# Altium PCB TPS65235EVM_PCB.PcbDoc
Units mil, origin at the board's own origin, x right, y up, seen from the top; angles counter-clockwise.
Board outline 3250 x 2250 mil, 2 copper layers (Top Layer, Bottom Layer), stack 62 mil thick; 65 components, 24 nets, 134 pads, 71 vias.
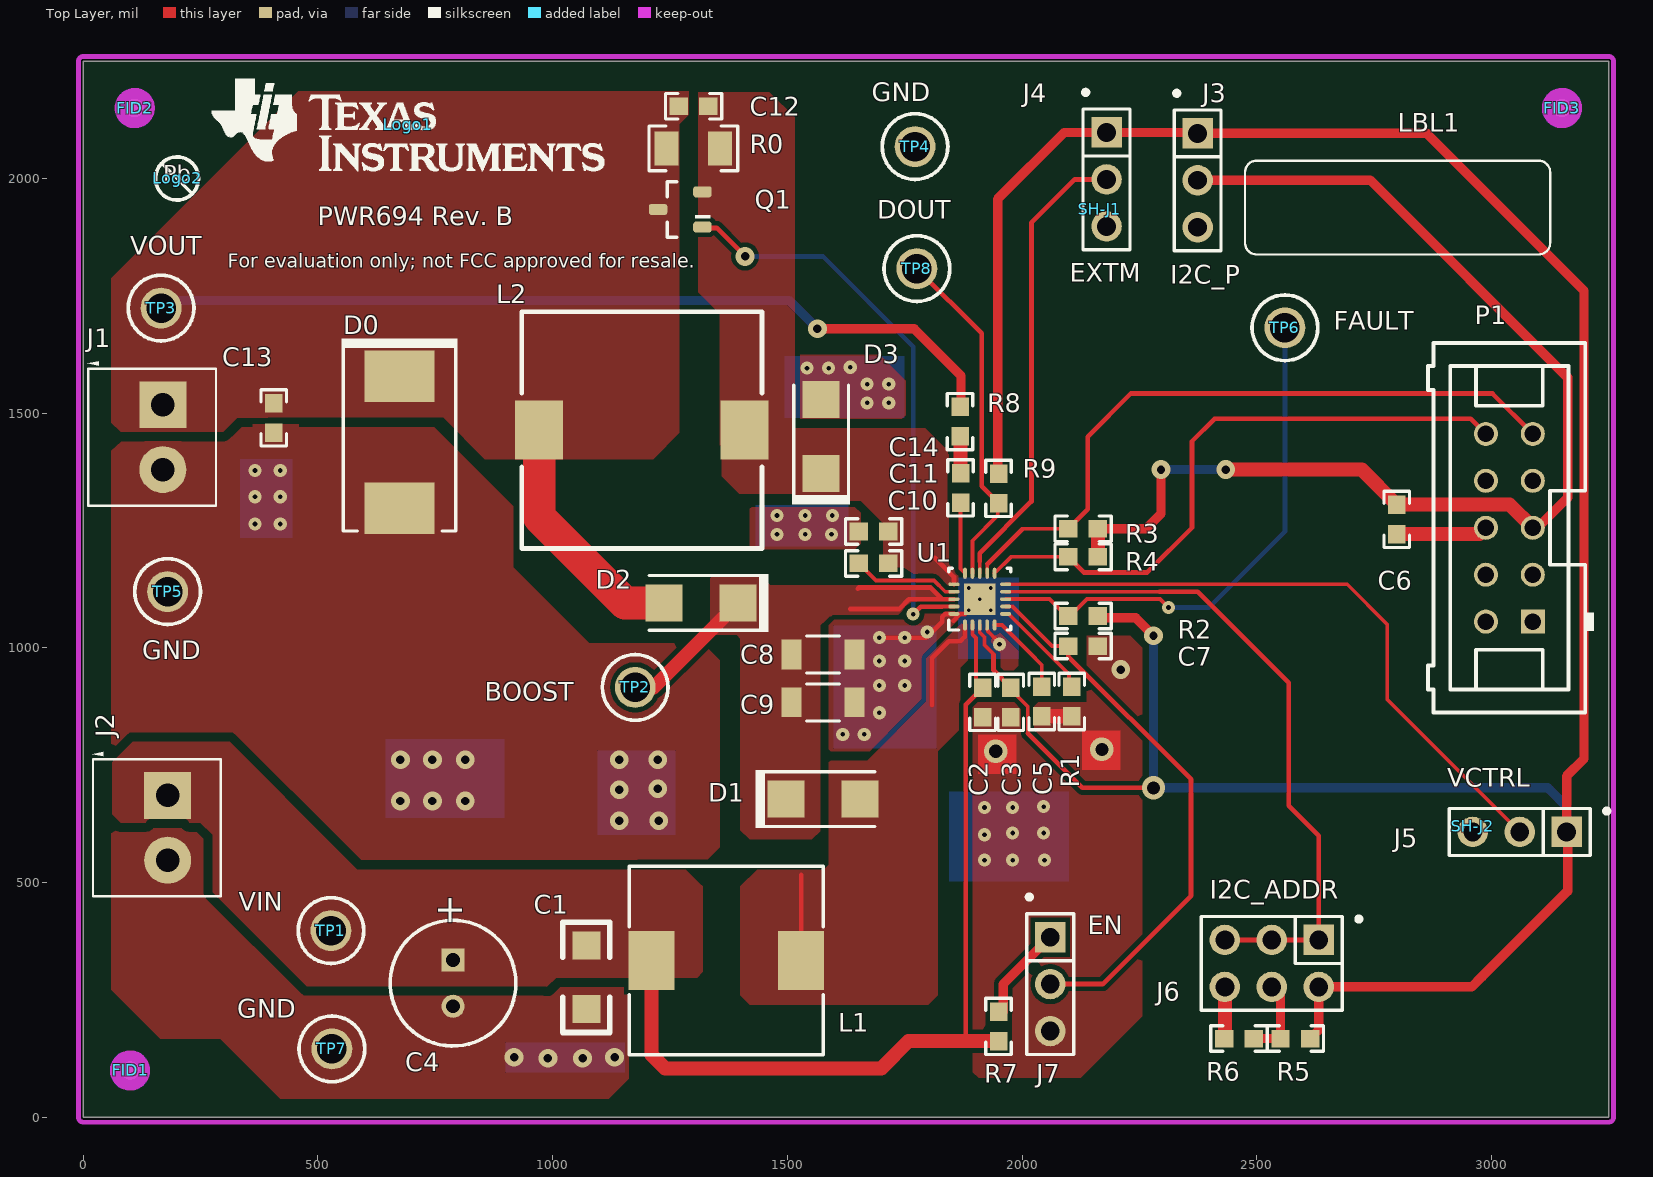
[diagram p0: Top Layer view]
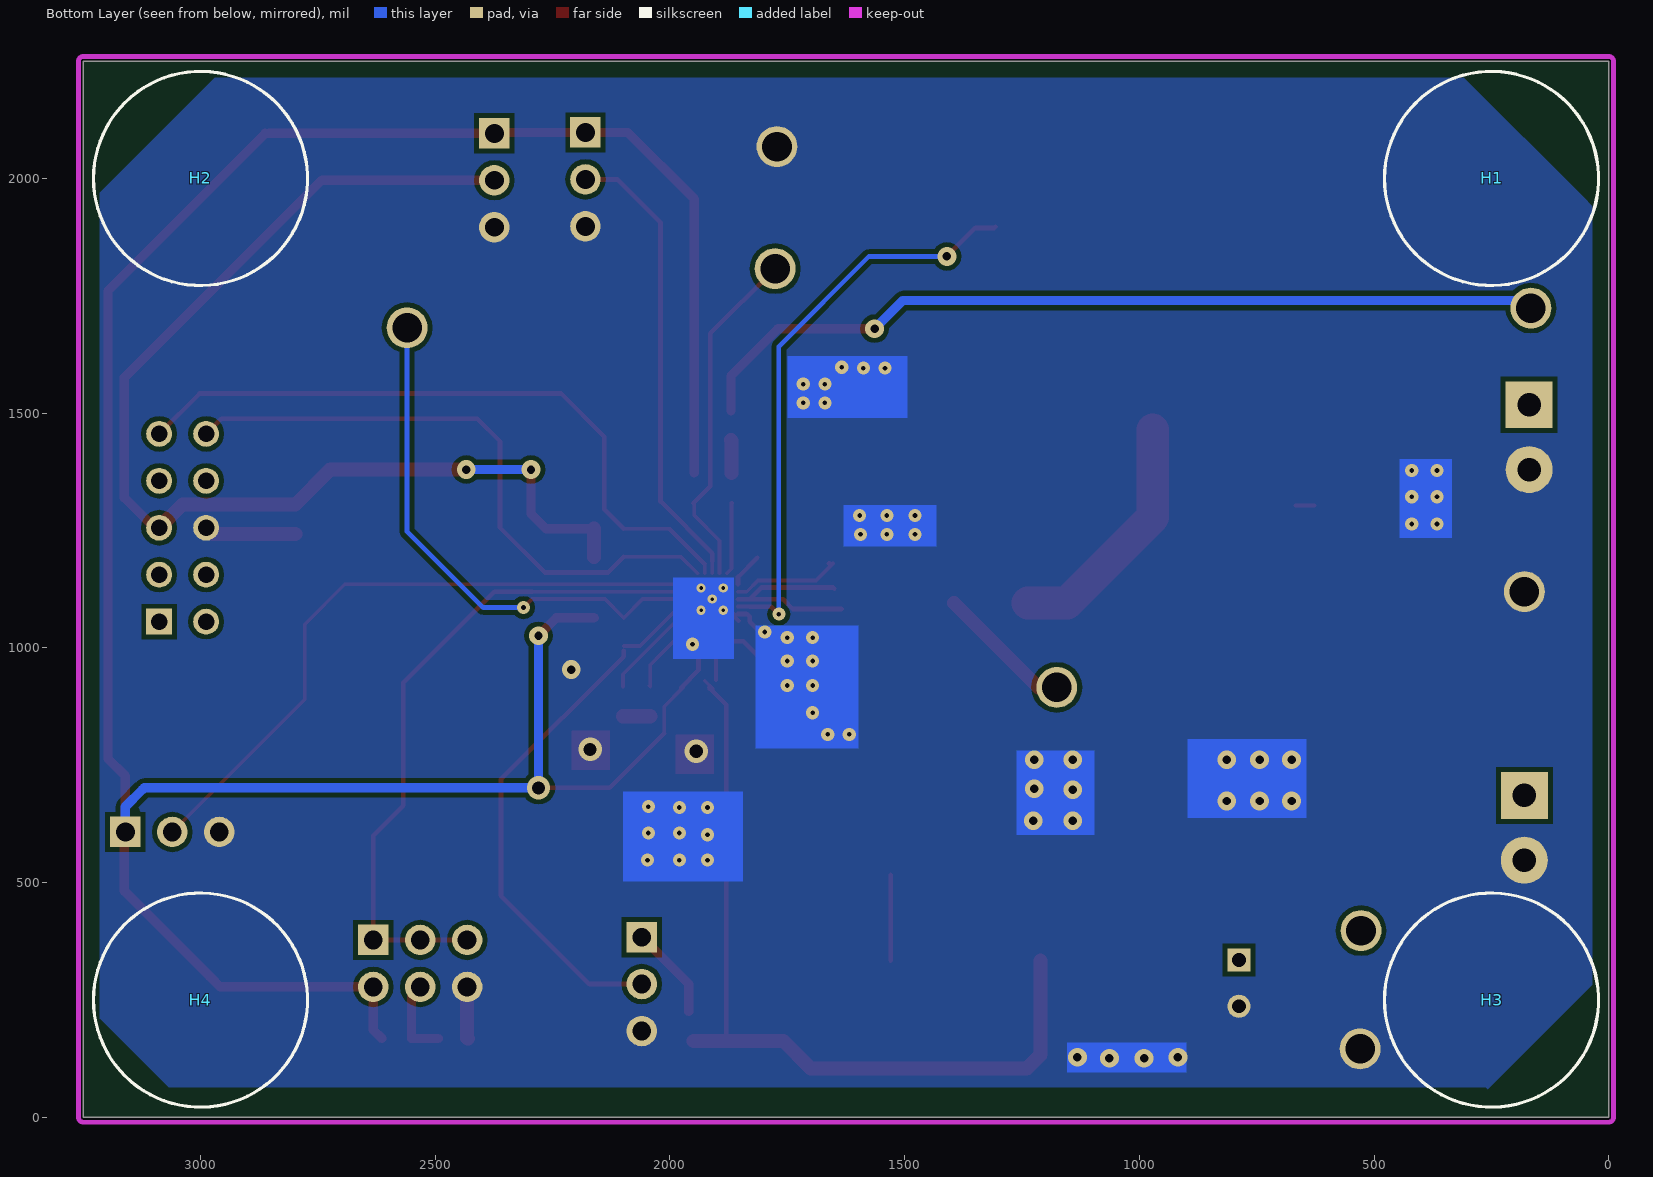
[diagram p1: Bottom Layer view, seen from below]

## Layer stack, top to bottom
Top Solder: solder mask 0.4, Solder Resist, Dk 3.5
Top Layer: signal copper 1.4
Dielectric1: core 59.2, FR-4, Dk 4.8
Bottom Layer: signal copper 1.4
Bottom Solder: solder mask 0.4, Solder Resist, Dk 3.5

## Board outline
0,0 0,2250 3250,2250 3250,0

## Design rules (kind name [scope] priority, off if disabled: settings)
AcuteAngle [All] p1: minimum=4.50000000000000E+0001 checktracksonly=FALSE
AssemblyTestPointUsage [All] p1: valid=2
Clearance Clearance_Keepouts [((IsTrack Or IsArc) And Not InPoly) And IsFree and IsKeepOut vs ((IsTrack Or IsArc) And Not InPoly) And IsFree and IsKeepOut] p1: gap=10
Clearance Clearance_BoardEdge_MountingHoles [OnCopper and InComponentClass('Mounting Holes') vs IsKeepOut] p2: gap=10
Clearance Clearance_BoardEdge_Poly [OnCopper and InPoly vs IsKeepOut] p3: gap=25
Clearance Clearance_BoardEdge [OnCopper and Not InComponentClass('Logo') and not InComponentClass('FiducialMark') and not InRegion(1000,500,4000,800) and Not IsKeepout vs IsKeepOut] p4: gap=30
Clearance Clearance_Poly [InPolygon] p5: gap=10
Clearance [All] p6: gap=6
ComponentClearance ComponentClearance_MountingHoles_FiducialMarks [InComponentClass('Mounting Holes') vs InComponentClass('FiducialMark')] p1: gap=20 collisioncheckmode=3 verticalgap=10 showdistances=FALSE
ComponentClearance ComponentClearance_Shunt [InComponentClass('Header') vs InComponentClass('Shunt')] p2: gap=0 collisioncheckmode=3 verticalgap=0 showdistances=FALSE
ComponentClearance ComponentClearance_Logo [InComponentClass('Logo')] p3: gap=20 collisioncheckmode=3 verticalgap=10 showdistances=FALSE
ComponentClearance ComponentClearance_ScrewToNut [(HasFootprint('NY PMS 440 0025 PH')) vs (HasFootprint('Keystone_1902C'))] p4: gap=5 collisioncheckmode=3 verticalgap=10 showdistances=FALSE
ComponentClearance ComponentClearance_MountingHoles [InComponentClass('Mounting Holes')] p5: gap=20 collisioncheckmode=3 verticalgap=100000 showdistances=FALSE
ComponentClearance ComponentClearance_SmallPassives [HasFootprint('0201*') or HasFootprint('0402*') or HasFootprint('0508') or HasFootprint('0603*') or HasFootprint('0612') or HasFootprint('0805*') or HasFootprint('0815*') or HasFootprint('0830*') or HasFootprint('1206*') or HasFootprint('1210*') or HasFootprint('1808*') or HasFootprint('1812*') or HasFootprint('1825*') or HasFootprint('2010*') or HasFootprint('2220*') or HasFootprint('2225*') or HasFootprint('2512*') or HasFootprint('2728*') or HasFootprint('3518*') vs HasFootprint('0201*') or HasFootprint('0402*') or HasFootprint('0508') or HasFootprint('0603*') or HasFootprint('0612') or HasFootprint('0805*') or HasFootprint('0815*') or HasFootprint('0830*') or HasFootprint('1206*') or HasFootprint('1210*') or HasFootprint('1808*') or HasFootprint('1812*') or HasFootprint('1825*') or HasFootprint('2010*') or HasFootprint('2220*') or HasFootprint('2225*') or HasFootprint('2512*') or HasFootprint('2728*') or HasFootprint('3518*')] p6: gap=20 collisioncheckmode=3 verticalgap=10 showdistances=FALSE
ComponentClearance ComponentClearance_THtoSMT [IsThruComponent vs IsSMTComponent] p7: gap=20 collisioncheckmode=3 verticalgap=30 showdistances=FALSE
ComponentClearance ComponentClearance_THtoTH [IsThruComponent vs IsThruComponent] p8: gap=20 collisioncheckmode=3 verticalgap=30 showdistances=TRUE
ComponentClearance [All] p9: gap=20 collisioncheckmode=3 verticalgap=10 showdistances=FALSE
DiffPairsRouting [All] p1: maxlimit=100 minlimit=10 mostfreqgap=10 toplayer_minwidth=15 toplayer_maxwidth=15 toplayer_prefwidth=15 bottomlayer_minwidth=15 bottomlayer_maxwidth=15 bottomlayer_prefwidth=15 maxuncoupledlength=1000
FabricationTestPointUsage TestPointUsage [All] p1: valid=2 allowmultiple=FALSE
FabricationTestpoint Testpoint [All] p1: side=3 testpointundercomponent=TRUE minsize=40 maxsize=100 preferedsize=60 minholesize=0 maxholesize=40 preferedholesize=32 testpointgrid=1 allowsidetop=TRUE allowsidebottom=TRUE usegrid=TRUE gridtolerance=0.01
FanoutControl Fanout_LCC [IsLCC] p1: bgadir=Out bgaviamode=Centered fanoutstyle=Auto fanoutdirection=Alternating viagrid=1 // Fanout_LCC (Default Rule)
FanoutControl Fanout_BGA [IsBGA] p2: bgadir=Out bgaviamode=Centered fanoutstyle=Auto fanoutdirection=Alternating viagrid=1 // Fanout_BGA (Default Rule)
FanoutControl Fanout_Default [All] p4: bgadir=Out bgaviamode=Centered fanoutstyle=Auto fanoutdirection=Alternating viagrid=1 // Fanout_Default (Default Rule)
FanoutControl Fanout_Small [(CompPinCount < 5)] p5: bgadir=Out bgaviamode=Centered fanoutstyle=Auto fanoutdirection=OutThenIn viagrid=1 // Fanout_Small (Default Rule)
HoleSize [All] p1: absolutevalues=TRUE maxlimit=251 minlimit=6 maxpercent=80.000 minpercent=20.000
HoleToHoleClearance [All] p1: gap=6 allowstackedmicrovias=TRUE
MinimumAnnularRing MinimumAnnularRing_ThermalPadVias [IsVia and InAnyComponent] p1: minimumring=5
MinimumAnnularRing [All] p2: minimumring=5
MinimumSolderMaskSliver MinimumSolderMaskSliver_Logo [InComponentClass('Logo') vs InComponentClass('Logo')] p1: minsoldermaskwidth=0.7
MinimumSolderMaskSliver [All] p2: minsoldermaskwidth=3.94
PlaneClearance [All] p1: clearance=10
PlaneConnect [All] p1: planeconnectstyle=Relief reliefexpansion=10 reliefentries=4 reliefconductorwidth=20 reliefairgap=10
PolygonConnect [All] p1: connectstyle=Direct reliefconductorwidth=20 reliefentries=4 polygonreliefangle="90 Angle" airgapwidth=6
RoutingVias ThermalPadVias [IsVia and InAnyComponent] p1: holewidth=7.87 width=19.68 viastyle="Through Hole" minholewidth=6 minwidth=16 maxholewidth=50 maxwidth=50
RoutingVias [All] p2: holewidth=16 width=34 viastyle="Through Hole" minholewidth=6 minwidth=16 maxholewidth=40 maxwidth=65
SilkToBoardRegionClearance [All] p1 off:
SilkToSilkClearance SilkToSilkClearance_Pb-FreeLogo [(HasFootprint('Pb-Free_Overlay_Medium') OR HasFootprint('Pb-Free_Overlay_Small')) vs (HasFootprint('Pb-Free_Overlay_Medium') OR HasFootprint('Pb-Free_Overlay_Small'))] p1: silktosilkclearance=0
SilkToSilkClearance [All] p2: silktosilkclearance=5
SilkToSolderMaskClearance "Silk to Solder Mask Opening" [IsPad] p1: minsilkscreentomaskgap=1 clearancetoexposedcopper=TRUE
SolderMaskExpansion [All] p1: expansion=1.97
Width [All] p1: maxlimit=100 minlimit=6 preferedwidth=10 checkconnectedcopper=TRUE
13 further rules are at their usual default settings.

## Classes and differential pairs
component class PWR694B_Hardware: !PCB FID1 FID2 FID3 H1 H2 H3 H4 LBL1 Logo1 Logo2 Logo3 SH-J1 SH-J2 ZZ2 ZZ3 ZZ4 ""
component class Header: J3 J4 J5 J6 J7
component class PWR694B: C1 C2 C3 C4 C5 C6 C7 C8 C9 C10 C11 C12 C13 C14 D0 D1 D2 D3 J1 J2 J3 J4 J5 J6 J7 L1 L2 P1 Q1 R0 R1 R2 R3 R4 R5 R6 R7 R8 R9 TP1 TP2 TP3 TP4 TP5 TP6 TP7 TP8 U1
component class FiducialMark: FID1 FID2 FID3
component class AssemblyNote: ZZ2 ZZ3 ZZ4 ""
component class Logo: Logo1
component class Shunt: SH-J1 SH-J2
component class Label: LBL1

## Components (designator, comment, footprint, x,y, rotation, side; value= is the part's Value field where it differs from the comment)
C1 "GRM31CR61E106KA12L" 1206#1 1072,366 r270 top
C2 "GRM188R61E105KA12D" 0603 1916,884 r270 top
C3 "GRM188R61E105KA12D" 0603 1976,884 r270 top
C4 "EEU-EB1E101S" CAPPR250W50D630H1120 788,286 r270 top
C5 "GRM188R71H223KA01D" 0603 2042,886 r90 top
C6 "GRM188R61E105KA12D" 0603 2798,1274 r270 top
C7 "GRM188R71H103KA01D" 0603 2130,1004 r0 top
C8 "C3216X5R1V226M160AC" 1206_180 1576,986 r0 top
C9 "C3216X5R1V226M160AC" 1206_180 1576,884 r0 top
C10 "0603YC104JAT2A" 0603 1684,1180 r0 top
C11 "GRM188R71H104KA93D" 0603 1684,1248 r180 top
C12 "GRM188R71H223KA01D" 0603 1300.31,2154 r180 top
C13 "GRM188R71H104KA93D" 0603 406,1490 r270 top
C14 "GRM188R71H103KA01D" 0603 1869,1341 r90 top
D0 "SMCJ28A" SMC 674,1438 r270 top
D1 "B340A-13-F" SMA 1576,678 r0 top
D2 "B240A-13-F" SMA 1316,1096 r180 top
D3 "B240A-13-F" SMA 1572,1450 r90 top
FID1 "Fiducial" Fiducial10-20 100,100 r0 top
FID2 "Fiducial" Fiducial10-20 110,2150 r0 top
FID3 "Fiducial" Fiducial10-20 3150,2150 r0 top
H1 "SJ-5303 (CLEAR)" Bumpon_SJ5003Transparent 250,2000 r180 bottom
H2 "SJ-5303 (CLEAR)" Bumpon_SJ5003Transparent 3000,2000 r180 bottom
H3 "SJ-5303 (CLEAR)" Bumpon_SJ5003Transparent 250,250 r180 bottom
H4 "SJ-5303 (CLEAR)" Bumpon_SJ5003Transparent 3000,250 r180 bottom
J1 "ED555/2DS" TERM_BLK_ED555-2DS 170,1518 r270 top
J2 "ED555/2DS" TERM_BLK_ED555-2DS 180,686 r270 top
J3 "TSW-103-07-G-S" TSW-103-07-G-S 2374,1996 r270 top
J4 "TSW-103-07-G-S" TSW-103-07-G-S 2180,1998 r270 top
J5 "TSW-103-07-G-S" TSW-103-07-G-S 3060,608 r180 top
J6 "TSW-103-07-G-D" TSW-103-07-G-D 2532,328 r180 top
J7 "TSW-103-07-G-S" TSW-103-07-G-S 2060,284 r270 top
L1 "CLF10040T-100M" CLF10040 1370,334 r0 top
L2 "SLF12565T-221M1R0-PF" SLF12565 1190,1464 r180 top
LBL1 "Size: 0.65\" x 0.20 \"" Label_650x200 2800,1938 r0 top
Logo1 "Texas Instruments" TI_Stacked_Overlay_Small 692,2114 r0 top
Logo2 "Pb-Free Symbol" Pb-Free_Overlay_Small 200,2000 r0 top
Logo3 "FCC disclaimer" FCC_disclaimer 3464,690 r90 top
P1 "XG4C-1031" OMRON_XG4C-1031 3038,1256 r180 top
Q1 "SI2316BDS-T1-E3" SOT-23 1272,1934 r180 top
R0 "CRCW120615R0FKEA" 1206#2 1300,2064 r0 top
R1 "CRCW0603110KFKEA" 0603 2106,886 r90 top
R2 "CRCW0603100KFKEA" 0603 2130,1068 r0 top
R3 "CRCW060310K0JNEA" 0603 2130,1254 r180 top
R4 "CRCW060310K0JNEA" 0603 2130,1194 r180 top
R5 "CRCW060333K0FKEA" 0603 2582,168 r0 top
R6 "CRCW0603100KFKEA" 0603 2462,168 r0 top
R7 "CRCW0603100KFKEA" 0603 1950,194 r270 top
R8 "CRCW060310K0JNEA" 0603 1868,1482 r90 top
R9 "CRCW0603100KFKEA" 0603 1950,1340 r270 top
SH-J1 "969102-0000-DA" SNT-100-BK-G 2166,1934 r90 top
SH-J2 "969102-0000-DA" SNT-100-BK-G 2960,620 r180 top
TP1 "5010" Keystone5010 528,398 r0 top
TP2 "5010" Keystone5010 1176,916 r0 top
TP3 "5010" Keystone5010 166,1724 r90 top
TP4 "5012" Keystone5012 1772,2068 r0 top
TP5 "5012" Keystone5012 180,1120 r90 top
TP6 "5012" Keystone5012 2560,1682 r0 top
TP7 "5012" Keystone5012 530,146 r90 top
TP8 "5012" Keystone5012 1776,1808 r0 top
U1 "TPS65235-1RUKR" RUK0020B 1910,1104 r90 top
ZZ1 "This Assembly Note is for PCB labels only" AssemblyNoteLabel 182.91,3919.84 r0 top
ZZ2 "These assemblies are ESD sensitive, ESD precautions shall be observed." AssemblyNote 185,3829.11 r0 top
ZZ3 "These assemblies must be clean and free from flux and all contaminants. Use of no clean flux is not acceptable." AssemblyNote 185,3740.56 r0 top
ZZ4 "These assemblies must comply with workmanship standards IPC-A-610 Class 2, unless otherwise specified." AssemblyNote 185,3652 r0 top

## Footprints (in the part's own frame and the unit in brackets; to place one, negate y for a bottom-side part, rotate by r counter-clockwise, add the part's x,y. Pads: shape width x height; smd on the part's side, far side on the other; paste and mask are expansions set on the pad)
0603 [mm] "0603 from SM-752 data"
  rect 1x0.95 smd: 1(-0.8,0) 2(0.8,0)
  silkscreen extent -1.52,-0.69 1.52,0.69, body extent -0.87,-0.47 0.87,0.47, height 0.85
1206#1 [mil]
  rect 60x60 smd: 1(0,0) 2(135,0)
  silkscreen extent -50,-50 185,50
1206#2 [mil] "1206 from SM-752 data"
  rect 51.18x72.83 smd: 1(-57.09,0) 2(57.09,0)
  silkscreen extent -94,-48 94,48, body extent -67,-35 67,35, height 53
1206_180 [mm] "1206_180"
  rect 1.1x1.6 smd: 1(-1.7,0) 2(1.7,0)
  silkscreen extent -0.9,-1 0.9,1, body extent -1.75,-0.95 1.75,0.95, height 1.8
AssemblyNote [mil] "Assembly Note"
AssemblyNoteLabel [mil] "Assembly Note for PCB Labels"
Bumpon_SJ5003Transparent [mil] "3M Hemispherical Bumpon transparent"
  round 1 on Mech4: 0(0,0)
  silkscreen extent -228,-228 228,228, body extent -217,-218 219,218, height 197
CAPPR250W50D630H1120 [mm] "PANASONIC"
  rect 1.25x1.25 hole 0.75: 1(-1.25,0)
  round 1.25 hole 0.75: 2(1.25,0)
  silkscreen extent -3.4,-3.4 3.4,3.4, body extent -3.37,-3.39 3.4,3.39, height 12.21
CLF10040 [mm] "TDK"
  rect 2.5x3.2 smd: 1(-4.05,0) 2(4.05,0)
  silkscreen extent -5.25,-5.1 5.25,5.1, body extent -5.15,-5 5.15,5, height 4.1
FCC_disclaimer [mil]
Fiducial10-20 [mm]
  round 1 smd mask+0.5: 1(0,0)
  Top Layer keep-out circle w1.178: c0,0 r0.5
Keystone5010 [mil] "Keystone Multipurpose loops"
  round 87 hole 63: 1(0,0)
  silkscreen extent -70,-70 70,70, body extent -63,-63 63,62, height 319
Keystone5012 [mil] "Keystone Multipurpose loops"
  round 87 hole 63: 1(0,0)
  silkscreen extent -70,-70 70,70, body extent -63,-63 63,62, height 319
Label_650x200 [mil] "Thermal Transfer Label"
  round 1 on Mech13: 0(0,0)
  silkscreen extent -325,-100 325,100, body extent -325,-100 325,100, height 1
OMRON_XG4C-1031 [mm] "TH, 10-Leads, Body 8.5x20mm, Pitch 2.54mm"
  rect 1.3x1.3 / inner round 1.4 / far side rect 1.4x1.4 hole 0.9: 1(-1.27,5.08)
  round 1.3 / inner round 1.4 / far side round 1.4 hole 0.9: 2(1.27,5.08) 3(-1.27,2.54) 4(1.27,2.54) 5(-1.27,0) 6(1.27,0) 7(-1.27,-2.54) 8(1.27,-2.54) 9(-1.27,-5.08) 10(1.27,-5.08)
  silkscreen extent -4.57,-10 4.4,10, body extent -4.1,-10 4.4,10, height 9.02
Pb-Free_Overlay_Small [mil]
  silkscreen extent -46,-46 46,46
RUK0020B [mm]
  oval 0.6x0.2 smd: 1(-1.4,0.8) 2(-1.4,0.4) 3(-1.4,0) 4(-1.4,-0.4) 5(-1.4,-0.8) 11(1.4,-0.8) 12(1.4,-0.4) 13(1.4,0) 14(1.4,0.4) 15(1.4,0.8)
  oval 0.2x0.6 smd: 6(-0.8,-1.4) 7(-0.4,-1.4) 8(0,-1.4) 9(0.4,-1.4) 10(0.8,-1.4) 16(0.8,1.4) 17(0.4,1.4) 18(0,1.4) 19(-0.4,1.4) 20(-0.8,1.4)
  rect 1.7x1.7 smd paste-0.85: 21(0,0)
  silkscreen extent -1.68,-1.68 1.68,1.68, body extent -1.55,-1.55 1.55,1.55, height 0.81
SLF12565 [mm] "TDK recommended land pattern"
  rect 2.6x3.2 smd: 1(-5.55,0) 2(5.55,0)
  silkscreen extent -6.5,-6.4 6.5,6.4, body extent -6.4,-6.4 6.4,6.4, height 6.85
SMA [mm] "Molded Diode, 2-Leads, Body 4.3x2.6mm, IPC Medium Density, based on OnSemi component dimensions and land pattern"
  rect 2x2 smd: 1(-2,0) 2(2,0)
  silkscreen extent -3.66,-1.57 2.79,1.57, body extent -2.6,-1.3 2.6,1.3, height 2.42
SMC [mil] "Molded Diode, 2-Leads, Body 6.9x5.8mm, IPC Medium Density, based on OnSemi component dimensions and land patterns"
  rect 110x150 smd: 1(-140.49,0) 2(140.49,0)
  silkscreen extent -221,-124 189,123, body extent -156,-116 156,116, height 91
SNT-100-BK-G [mil] "Samtec STEP model"
  round 1 on Mech3: 0(0,0)
  body extent -100,-50 100,50, height 344
SOT-23 [mm] "SOT23, 3-Leads, Body 2.9x1.3mm, Pitch 0.95mm, Lead Span 2.5mm, IPC Medium Density"
  rrect50% 1x0.6 smd: 1(-1.2,0.95) 2(-1.2,-0.95) 3(1.2,0)
  silkscreen extent -1.63,-1.5 0.7,1.5, body extent -1.16,-1.45 1.21,1.45, height 1
TERM_BLK_ED555-2DS [mil]
  rect 100x100 hole 50: 1(0,0)
  round 100 hole 50: 2(138,0)
  silkscreen extent -93,-161 215,113, body extent -69,-150 207,106, height 323
TI_Stacked_Overlay_Small [mil]
  silkscreen extent -418,-98 418,98
TSW-103-07-G-D [mm] "Samtec 100mil, 2x3, 230 mil above insulator"
  rect 1.65x1.65 hole 1.016: 1(-2.54,-1.27)
  round 1.65 hole 1.016: 2(-2.54,1.27) 3(0,-1.27) 4(0,1.27) 5(2.54,-1.27) 6(2.54,1.27)
  silkscreen extent -4.84,-2.54 3.81,2.54, body extent -3.81,-2.54 3.81,2.54, height 8.38
TSW-103-07-G-S [mm] "Samtec 100mil, 1x3, 230 mil above insulator"
  rect 1.65x1.65 hole 1.016: 1(-2.54,0)
  round 1.65 hole 1.016: 2(0,0) 3(2.54,0)
  silkscreen extent -4.83,-1.27 3.81,1.27, body extent -3.81,-1.27 3.81,1.27, height 8.38

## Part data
C1: "CAP, CERM, 10 μF, 25 V, +/- 10%, X5R, 1206"
C2 C3 C6: "CAP, CERM, 1 μF, 25 V, +/- 10%, X5R, 0603"
C4: "CAP, AL, 100 μF, 25 V, +/- 20%, TH"
C5 C12: "CAP, CERM, 0.022 μF, 50 V, +/- 10%, X7R, 0603"
C7 C14: "CAP, CERM, 0.01 μF, 50 V, +/- 10%, X7R, 0603"
C8 C9: "CAP, CERM, 22 μF, 35 V, +/- 20%, X5R, 1206"
C10: "CAP, CERM, 0.1 μF, 16 V, +/- 5%, X7R, 0603"
C11 C13: "CAP, CERM, 0.1 μF, 50 V, +/- 10%, X7R, 0603"
D0: "Diode, TVS, Uni, 28 V, 1500 W, SMC"
D1: "Diode, Schottky, 40 V, 3 A, SMA"
D2 D3: "Diode, Schottky, 40 V, 2 A, SMA"
FID1 FID2 FID3: "Fiducial mark.  There is nothing to buy or mount."
H1 H2 H3 H4: "Bumpon, Hemisphere, 0.44 X 0.20, Clear"
J1 J2: "Terminal Block, 6A, 3.5mm Pitch, 2-Pos, TH"
J3 J4 J5 J7: "Header, 100mil, 3x1, Gold, TH"
J6: "Header, 100mil, 3x2, Gold, TH"
L1: "Inductor, Shielded, Ferrite, 10 μH, 4 A, 0.0312 ohm, SMD"
L2: "Inductor, Shielded, Ferrite, 220 μH, 1.2 A, 0.273 ohm, SMD"
LBL1: library part THT-14-423-10, "Thermal Transfer Printable Labels, 0.650\" W x 0.200\" H - 10,000 per roll"
Logo1: library part TI_Logo, "Texas Instrument Corporate Signature"
Logo2: library part Pb-Free
Logo3: library part FCC_disclaimer, "FCC_disclaimer"
P1: "Header (shrouded), 100mil, 5x2, Gold, TH"
Q1: "MOSFET, N-CH, 30 V, 4.5 A, SOT-23"
R0: "RES, 15.0, 1%, 0.25 W, 1206"
R1: "RES, 110 k, 1%, 0.1 W, 0603"
R2 R6 R7 R9: "RES, 100 k, 1%, 0.1 W, 0603"
R3 R4 R8: "RES, 10 k, 5%, 0.1 W, 0603"
R5: "RES, 33.0 k, 1%, 0.1 W, 0603"
SH-J1 SH-J2: "Shunt, 100mil, Gold plated, Black"
TP1 TP2 TP3: "Test Point, Multipurpose, Red, TH"
TP4 TP5 TP6 TP7 TP8: "Test Point, Multipurpose, White, TH"
U1: "LNB VOLTAGE REGULATOR WITH I2C INTERFACE, RUK0020B"
ZZ1: library part AssemblyNoteLabel
ZZ2 ZZ3 ZZ4: library part AssemblyNote

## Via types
v1: diameter 28, hole 10, Top Layer to Bottom Layer, 41 vias
v2: diameter 40, hole 18, Top Layer to Bottom Layer, 22 vias
v3: diameter 19.68, hole 7.87, Top Layer to Bottom Layer, 5 vias
v4: diameter 50, hole 28, Top Layer to Bottom Layer, 3 vias

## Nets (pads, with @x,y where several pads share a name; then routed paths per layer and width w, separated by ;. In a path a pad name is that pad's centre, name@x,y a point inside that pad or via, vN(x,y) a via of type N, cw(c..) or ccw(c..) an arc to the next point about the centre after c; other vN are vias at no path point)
ADDR: J6.1 J6.3 J6.5 U1.9 | length 1457.6
  Top Layer w8: U1.9 2292,1119.75
  Top Layer w10: 2292,1119.75 2374.25,1119.75 2568,926 2568,664 2632,600 J6.1 J6.3 J6.5
BOOST: C8.1 C9.1 D1.1 D2.1 TP2.1 U1.18 | length 714.1
  Top Layer w10: 1634,1082.93 1738,1082.93 1759.07,1104 1829.81,1104 ; 1650,1126 1652.71,1128.71 1805.11,1128.71 1829.81,1104 ; U1.18 1829.81,1104
  Top Layer w30: TP2.1 1214.74,916 D2.1
DIN: C14.1 U1.15 | length 155.7
  Top Layer w8: C14.1@1868,1308.5 C14.1 1869,1168.62 U1.15
DOUT: R9.2 TP8.1 U1.14 | length 744.2
  Top Layer w8: U1.14 1894.25,1228.25 1948,1282 R9.2@1948,1309.5
  Top Layer w10: TP8.1 1914,1670 1914,1344.5 R9.2
EN: C7.1 J7.2 U1.7 | length 1176.5
  Top Layer w8: U1.7 1979.75,1088.25 2064,1004 C7.1
  Top Layer w10: J7.2 2172,284 2360,472 2360,720 2098.5,981.5 C7.1@2098.5,994
EXTM: J4.2 U1.13 | length 990.6
  Top Layer w8: U1.13 1910,1184
  Top Layer w10: 1910,1184 1910,1202 2020,1312 2020,1906 2112,1998 J4.2
FAULT: R2.1 TP6.1 U1.8 | length 1136.6
  Top Layer w8: U1.8 2058.5,1104 2098.5,1064 2138.5,1104 2294,1104 v1(2312,1086)
  Bottom Layer w10: v1(2312,1086) 2398,1086 2560,1248 TP6.1
GDR: Q1.1 U1.19 | length 1231
  Top Layer w8: 1829.37,1088.25 U1.19
  Top Layer w10: Q1.1@1306.35,1897.5 1309.26,1894.6 1349.4,1894.6 v2(1410,1834) ; v1(1768,1072) 1784,1088 1829.37,1088
  Bottom Layer w10: v2(1410,1834) 1576,1834 1768,1642 v1(1768,1072)
GND: C1.2 C2.2 C3.2 C4.2 C5.1 C6.2 C7.2 C8.2 C9.2 C11.2 C13.2 D0.2 D3.2 J1.2 J2.2 J3.3 J4.3 J5.3 J6.6 J7.3 P1.6 R1.1 R6.1 TP4.1 TP5.1 TP7.1 U1.4 U1.20 U1.21 | length 732
  Top Layer w8: D0.2@627,1303.51 D0.2@668,1303.51 ; U1.21@1878.5,1072.5 v3(1886.38,1080.38) v3(1910,1104) ; U1.4@1926,1041.59 1926,1037.6 1927.56,1036.04 1927.56,1035.24 1935.72,1027.07 ; 1936,1026.79 1952,1010.79 1952,996 1946,1002 v1(1952,1008)
  Top Layer w10: v1@1706.93,1022 1796,1022 1830,1056 1830,1066 1836.5,1072.5 U1.20 ; 1854,1058 1864.5,1068.5 1864.5,1072.5 U1.21@1878.5,1072.5 ; v4(2170,784) v4@2170,784.5
  Top Layer w30: D3.2 D3.2@1572,1530 ; C5.1 R1.1@2100,854.5 ; R6.1 2432,169.5 J6.6 ; C6.2 2974.5,1242.5 P1.6
  other v1: 1920,548 1980,548 2048,548 1920,602 1980,606 2046,606 1920,660 1980,660 2046,662 1618,816 1664,816 1696,862 1696,920 1750,920 1696,972 1750,972 1696,1022 1750,1022 1798,1034 1478,1242 1538,1242 1594,1242 366,1264 420,1264 1478,1282 1538,1282 1596,1282 366,1322 420,1322 366,1378 420,1378 1670,1522 1716,1522 1670,1562 1716,1562 1542,1596 1588,1596 1634,1598
  other v2: 990,126 1064,126 918,128 1132,128 1142,632 1226,632 676,674 744,674 814,674 1142,698 1224,700 676,762 744,762 814,762 1142,762 1224,762 2210,954
  other v3: 1933.62,1080.38 1886.38,1127.62 1933.62,1127.62
  other v4: 1944,780
ISET: R1.2 U1.6 | length 214.6
  Top Layer w8: U1.6 1971.5,1072.5 2070,974 2100,944 R1.2@2100,917.5
LX: D1.2 L1.2 U1.1 | length 396.7
  Top Layer w10: L1.2 1529.45,516.55 ; 1808,878 1808,978 1844,1014 1868,1014 1878.5,1024.5 U1.1
NetC14_2: C14.2 R8.1 | length 70.4
  Top Layer w30: C14.2 1869,1441.5 R8.1@1870,1442.5
NetJ6_4: J6.4 R5.1 R6.2 | length 174.7
  Top Layer w20: R6.2 R5.1 2550.5,259.5 J6.4
NetJ7_1: J7.1 R7.1 | length 199.9
  Top Layer w20: R7.1@1960,225.5 1960,284 J7.1
SCL: P1.9 R3.2 U1.12 | length 1457.8
  Top Layer w8: U1.12 1925.75,1178.53 1926.56,1179.35 ; 2000,1254 R3.2
  Top Layer w10: 1926.56,1179.35 2000,1252.79 ; R3.2 2140,1295.5 2140,1449.99 2232.01,1541.99 3002.01,1541.99 P1.9
SDA: P1.10 R4.2 U1.11 | length 1331.2
  Top Layer w8: U1.11 1976.38,1194 R4.2
  Top Layer w10: R4.2 2131.63,1160.87 2266.87,1160.87 2362,1256 2362,1440 2410,1488 2956,1488 P1.10
TCAP: C5.2 U1.5 | length 185
  Top Layer w8: U1.5 1957.12,1048.88 2016,990 2042,964 C5.2 C5.2@2044,919.5
V3V: C6.1 J3.2 P1.5 R3.1 R4.1 | length 2471.6
  Top Layer w10: P1.5 P1.5@3098,1256
  Top Layer w20: R3.1 2264,1254 2296,1286 v2(2296,1380) ; J3.2@2364,2002 J3.2@2372,2002 ; J3.2 2742,1996 3162,1576 3162,1320 P1.5@3098,1256
  Top Layer w30: R4.1 R3.1 ; v2(2434,1380) 2723.5,1380 C6.1 3038.5,1305.5 P1.5
  Bottom Layer w20: v2(2296,1380) v2(2434,1380)
VCC: C3.1 J3.1 J4.1 J5.1 J6.2 R2.2 R5.2 R9.1 U1.3 | length 6026.9
  Top Layer w8: U1.3 1910,1033 1920,1023 1920,1006.06 1940,986.06 ; C3.1@1972,915.5 2012,875.5 2012,818
  Top Layer w10: 1939.29,985.35 1939.29,952.2 C3.1 ; R9.1@1948,1373.5 R9.1 ; 2012,818 2128,702 v4(2280,702) ; J3.1@2360,2098 J3.1@2364,2102 ; 2854,2096 2862,2096 ; J5.1@3162,606 J5.1@3162.29,607.58
  Top Layer w20: R9.1@1948,1373.5 1948,1956 2090,2098 J4.1 J3.1@2360,2098 ; R2.2@2161.5,1064 2242,1064 v2(2280,1026) ; J3.1 2854,2096 ; R5.2 2632,186.5 J6.2 2958,278 2980,300 3162,482 J5.1@3162,606 ; 2862,2096 3197,1761 3197,764 3160,727 J5.1
  Bottom Layer w10: 3120,702 3124,698
  Bottom Layer w20: v4(2280,702) 3120,702 ; v4@2280,724 v2(2280,1026) ; 3124,698 3160,662 J5.1
VCP: C10.1 U1.17 | length 228
  Top Layer w8: C10.1 1688.8,1143.71 1696.64,1143.71 1812.29,1143.71 1836.25,1119.75 U1.17
  Top Layer w10: C10.1@1660.35,1180 C10.1@1661.05,1180
VCTRL: J5.2 U1.10 | length 1407.1
  Top Layer w8: U1.10 2540.5,1135.5 2692.5,1135.5 2778,1050 2778,890 J5.2
VIN: C1.1 C2.1 C4.1 J2.1 L1.1 R7.2 TP1.1 U1.2 | length 1892.1
  Top Layer w8: U1.2 1894.25,1028.94 1902,1021.2 C2.1@1902,932 ; C2.1@1909.5,913.5 C2.1@1926,930 ; C2.1@1916,912 C2.1
  Top Layer w10: 1878,162.5 1880,164.5 1880,879.5 C2.1
  Top Layer w30: L1.1 1210.55,133.45 1240,104 1700,104 1758.5,162.5 1878,162.5 R7.2
VLNB: C10.2 C11.1 C12.1 D3.1 L2.1 Q1.2 R0.2 U1.16 | length 73.4
  Top Layer w10: 1814,1192 1854.88,1151.12 U1.16
VOUT: C12.2 C13.1 D0.1 D2.2 J1.1 L2.2 Q1.3 R0.1 R8.2 TP3.1 | length 2360
  Top Layer w10: L2.2@971.26,1463.76 L2.2
  Top Layer w20: v2@1572,1680 1770,1680 1870,1580 R8.2@1870,1505.5
  Top Layer w70: L2.2 971.5,1278.5 1154,1096 D2.2
  Bottom Layer w20: TP3.1@170,1740 1504,1740 v2(1564,1680)
pads on no net: FID1.1 FID2.1 FID3.1 H1.0 H2.0 H3.0 H4.0 LBL1.0 P1.1 P1.2 P1.3 P1.4 P1.7 P1.8 SH-J1.0 SH-J2.0

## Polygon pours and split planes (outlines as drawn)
GND on Top Layer "Top Layer-No Net 10" (solid, remove dead copper, pour order 40): 60,1420 90,1450 318,1450 348,1480 738,1480 748.39,1469.61 916,1302 916,1172 1078,1010 1320,1010 1356,974 1356,576 1330,550 1180,550 1180,546 1162,528 1162,534 1162,82 1160,80 1120,40 420,40 292,168 164,168 162,170 60,272 60,1420 90,1450 92,1450
BOOST on Top Layer "Top Layer-No Net 8" (solid, remove dead copper, pour order 35): 1850,1110 1832,1110 1808,1134 1474,1134 1464,1134 1444,1154 1342,1154 1336,1148 1336,1048 1336,1040 1348,1028 1392,1028 1400,1020 1560,1020 1560,1038 1590,1068 1732,1068 1734,1068 1762,1096 1764,1098 1850,1098 1850,1110
GND on Top Layer "Top Layer-No Net 5" (solid, remove dead copper, pour order 32): 1530,1300 1424,1300 1420,1296 1420,1216 1420,1214 1424,1210 1534,1210 1534,1296 1530,1300
BOOST on Top Layer "Top Layer-No Net 3" (solid, remove dead copper, pour order 27): 1848,1108 1832,1108 1456,1108 1444,1108 1436,1100 1400,1064 1400,612 1420,592 1546,592 1552,592 1570,610 1570,1048 1594,1072 1598,1076 1736,1076 1738,1076 1762,1100 1848,1100 1848,1108
GND on Top Layer "Top Layer-No Net" (solid, remove dead copper, pour order 24): 1874,1080 1790,1080 1770,1060 1696,1060 1600,1060 1588,1048 1588,1046 1588,784 1592,780 1680,780 1770,870 1786,886 1786,980 1874,1068 1874,1080
GND on Top Layer "Top Layer-No Net 12" (solid, remove dead copper, pour order 34): 1528,1618 1528,1488 1744,1488 1750,1494 1752,1496 1752,1578 1752,1584 1714,1622 1712,1624 1528,1624 1528,1618
GND on Top Layer "Top Layer-No Net 21" (solid, remove dead copper, pour order 31): 952,198 1154,198 1162,190 1162,94 956,94 952,98 868,198
GND on Top Layer "Top Layer-No Net 9" (solid, remove dead copper, pour order 30): 361,1476 361,1470.93 333,1435.45 329,1430.38 329,1222.53 455,1222.53 457,1220 459,1222.53 459,1476 361,1476
VLNB on Top Layer "Top Layer-No Net 19" (solid, remove dead copper, pour order 29): 1596,1468 1768,1468 1794,1468 1828,1434 1844,1418 1844,1190 1844,1172 1842,1174 1704,1174 1704,1266 1656,1314 1514,1314 1514,1468 1598,1468
VLNB on Top Layer "Top Layer-No Net 18" (solid, remove dead copper, pour order 28): 1360,1468 1360,1366 1398,1328 1624,1328 1634,1328 1634,1430 1634,1432 1614,1452 1598,1468 1360,1468
GND on Top Layer "Top Layer-No Net 4" (solid, remove dead copper, pour order 25): 1924,1034 1924,976 1924,974 1944,954 1946,952 1970.69,952 1982,952 1990,960 1992,962 1992,1012 1964,1040 1962,1042 1924,1042 1924,1028
GND on Top Layer "Top Layer-No Net 13" (solid, remove dead copper, pour order 37): 1546,1300 1528,1282 1528,1274 1528,1234 1528,1230 1540,1218 1566,1218 1652,1218 1654,1220 1656,1222 1656,1274 1656,1288 1644,1300 1548,1300
GND on Top Layer "Top Layer-No Net 16" (solid, remove dead copper, pour order 39): 1878,686 1878,432 1886,424 1904,406 2126,406 2128,406 2154,432 2252,530 2252,696 2252,698 2194,756 2182,744 1878,744 1878,680
VOUT on Top Layer "Top Layer-No Net 11" (solid, remove dead copper, pour order 33): 60,1480 80,1460 298,1460 302,1464 328,1490 342,1490 768,1490 856,1402 1178,1402 1214,1402 1270,1458 1270,2116 1290,2136 1290,2186 458,2186 60,1788
VIN on Top Layer "Top Layer-No Net 14" (solid, remove dead copper, pour order 36): 62,756 104,798 106,800 308,800 312,800 548,564 584,528 1282,528 1284,528 1314,498 1320,492 1320,312 1320,310 1308,298 1032,298 1008,298 988,278 986.53,279.47 476.53,279.47 276,480 276,602 250,628 80,628 62,646 62,756
VLNB on Top Layer "Top Layer-No Net 20" (solid, remove dead copper, pour order 41): 1864,1134 1801.86,1134 1778,1158 1768,1158 1754.63,1167.66 1746.72,1171.63 1704,1171.63 1714.66,1165.9 1704,1174.83 1704,1208 1752,1208 1766,1222 1768,1224 1844,1224 1844,1178 1864,1158
GND on Top Layer "Top Layer-No Net 22" (solid, remove dead copper, pour order 43): 1514,1280 1514,1284 1530,1300 1644,1300 1656,1288 1656,1222 1648,1214 1644,1210 1528,1210 1524,1210 1514,1220 1514,1286
GND on Top Layer "Top Layer-No Net 25" (solid, remove dead copper, pour order 44): 2138,1026 2230,1026 2242,1014 2256,1000 2256,820 2138,820 2138,1026
GND on Top Layer "Top Layer-No Net 26" (solid, remove dead copper, pour order 45): 1906.13,884 1895.29,873.16 1895.29,96.71 1908,84 1908.81,84.81 2121.19,84.81 2124.81,84.81 2230,190 2256,216 2256,858.69 2256,864 2236,884 1906.13,884
VLNB on Top Layer "Top Layer-No Net 2" (solid, remove dead copper, pour order 42): 1312,2184 1420,2184 1462,2184 1516,2130 1516,1432 1356,1432 1356,1710 1356,1712 1312,1756 1310,1758 1310,2184
LX on Top Layer "Top Layer-No Net 6" (solid, remove dead copper, pour order 53): 1872,1056 1884,1056 1884,974 1868,958 1868,828 1864.71,824.71 1820,780 1820,260 1800,240 1420,240 1400,260 1400,492 1436,528 1572,528 1578,528 1588,538 1588,756 1592,760 1670,760 1796,886 1796,977.65 1796,980 1872,1056
GND on Bottom Layer "Bottom Layer-No Net 1" (solid, remove dead copper, pour order 38): 1634,912 1750,912 1750,806 1746,810 1634,810 1634,912
GND on Bottom Layer "Bottom Layer-No Net" (solid, remove dead copper, pour order 51): 556.28,2214.7 308.7,2214.7 54,1960 34,1940 34,310 34,284 258,60 262,64 3066,64 3068,64 3214,210 3214.7,210.7 3214.7,1970.09 2970.09,2214.7 2964.79,2220 556,2220

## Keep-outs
Keep-Out Layer:
  lines w10: -2,2260 3248,2260 ; 0,2260 ccw(c0,2250) -10,2250 -10,0 ; 3250,2260 cw(c3250,2250) 3260,2250 3260,0 ; -10,0 ccw(c0,0) 0,-10 ; -10,0 ccw(c0,0) 0,-10 ; 0,-10 3250,-10 ; 3250,-10 ccw(c3250,0) 3260,0 ; 3250,-10 ccw(c3250,0) 3260,0
  text ".Layer_Name" at 577,-858.49 h60

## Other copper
Top Layer:
  rectangle net BOOST: 1830,1100 1850,1108
  rectangle net GND: 1906,732 1988,816
  rectangle net GND: 2128,740 2210,824
  text ".Layer_Name" at 577,-858.49 h60
Bottom Layer:
  rectangle net GND: 1096,602 1262,782
  rectangle net GND: 1864,976 1994,1150
  rectangle net GND: 1432,1216 1630,1304
  rectangle net GND: 900,96 1154,160
  rectangle net GND: 1844,502 2100,694
  rectangle net GND: 1598,786 1818,1048
  rectangle net GND: 334,1234 446,1402
  rectangle net GND: 1494,1490 1750,1622
  rectangle net GND: 644,638 898,806
  text "SVN:" at 4400,288 h60
  text ".VersionControl_RevNumber" at 4498,100 h60
  text ".Layer_Name" at 577,-858.49 h60

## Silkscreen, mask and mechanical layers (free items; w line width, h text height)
Top Overlay:
  text "GND" at 1680,2164 h40
  text "DOUT" at 1692,1914 h40
  text "PWR694 Rev. B" at 500,1900 h40
  text "VOUT" at 100,1838 h40
  text "EXTM" at 2102,1780 h40
  text "I2C_P" at 2316,1776 h40
  text "FAULT" at 2664,1678 h40
  text "GND" at 126,976 h40
  text "BOOST" at 856,888 h40
  text "VCTRL" at 2906,704 h40
  text "I2C_ADDR" at 2400,466 h40
  text "VIN" at 332,440 h40
  text "EN" at 2140,390 h40
  text "GND" at 328,212 h40
  text ".Layer_Name" at 577,-858.49 h60
Bottom Overlay:
  text ".Layer_Name" at 577,-858.49 h60
Top Paste:
  text ".Layer_Name" at 577,-858.49 h60
Bottom Paste:
  text ".Layer_Name" at 577,-858.49 h60
Top Solder:
  text ".Layer_Name" at 577,-858.49 h60
  text ".Layer_Name" at 577,-858.49 h60
Bottom Solder:
  text ".Layer_Name" at 577,-858.49 h60
Drill Guide:
  text ".Layer_Name" at 577,-858.49 h60
M1 Board Outline:
  lines w10: 0,0 3250,0 3250,2250 0,2250 0,0 ; 2500,-5 ccw(c2500,0) 2505,0 cw(c2500,0) 2500,-5
  text ".Layer_Name" at 577,-858.49 h60
M2 Board Dimensions:
  rectangle: 0,-275 125,-150
  rectangle: 125,-400 500,-275
  lines w7: 0,-275 1000,-275 ; 125,-400 125,-150 ; 250,-400 250,-150 ; 500,-400 500,-150 ; 750,-400 750,-150 ; 0,-400 1000,-400 1000,-150 0,-150 0,-400
  text ".Layer_Name" at 577,-858.49 h60
M3 3D STEP Top:
  text ".Layer_Name" at 577,-858.49 h60
M4 3D STEP Bottom:
  text ".Layer_Name" at 577,-858.49 h60
M5 Assembly Top:
  lines w10: -292,-930.17 6308,-930.17 ; -292,-726.83 6310,-726.83 ; -292,-523.5 -292,-1133.5 3713,-1133.5 6310,-1133.5 6310,-523.5 -291.5,-523.5 -291.5,-1133.5 1284,-1133.5 ; 2173,-1133.5 2173,-523.5 ; 3440,-726.83 3440,-523.5 ; 4280,-726.83 4280,-523.5 ; 4902,-1140 4902,-937.17
  text "COMPONENTS MARKED 'DNP' SHOULD NOT BE POPULATED." at 1153.5,-318.5 h60
  text "ASSEMBLY VARIANT:" at 1153,-434 h60
  text ".VariantName" at 2189,-434 h60
  text "PCB VIEWED FROM TOP SIDE" at -228.5,-655.67 h60
  text "BOARD #:" at 2248,-655.67 h60
  text ".PRJ_Number" at 2793.5,-655.67 h60
  text "REV:" at 3638,-655.67 h60
  text ".PCB_Rev" at 3929.5,-655.67 h60
  text "SVN REV:" at 4476,-655.67 h60
  text ".VersionControl_RevNumber" at 4982,-655.67 h60
  text "PLOT NAME =" at -228.5,-1064.34 h60
  text ".plot_File_Name" at 577,-1064.34 h60
  text "GENERATED    :" at 2250,-1064.34 h60
  text ".Print_Date" at 3119.5,-1064.34 h60
  text ".Print_Time" at 3848.5,-1064.34 h60
  text "TEXAS INSTRUMENTS" at 5113,-1064.34 h60
M6 Assembly Bottom:
  lines w10: -292.5,-727.33 6309.5,-727.33 ; -290.5,-930.67 6309.5,-930.67 ; 1115.5,-1140.5 1115.5,-937.67 ; 1737.5,-727.33 1737.5,-524 ; 2577.5,-727.33 2577.5,-524 ; 3844.5,-1134 3844.5,-524 ; 4733.5,-1134 6309,-1134 6309,-524 -292.5,-524 -292.5,-1134 2304.5,-1134 6309.5,-1134 6309.5,-524
  text "COMPONENTS MARKED 'DNP' SHOULD NOT BE POPULATED." at 6102,-318 h60
  text ".VariantName" at 5058,-434 h60
  text "ASSEMBLY VARIANT:" at 6097,-434 h60
  text ".VersionControl_RevNumber" at 1035.5,-656.17 h60
  text "SVN REV:" at 1541.5,-656.17 h60
  text ".PCB_Rev" at 2088,-656.17 h60
  text "REV:" at 2379.5,-656.17 h60
  text ".PRJ_Number" at 3224,-656.17 h60
  text "BOARD #:" at 3769.5,-656.17 h60
  text "PCB VIEWED FROM BOTTOM SIDE" at 6246,-656.17 h60
  text "TEXAS INSTRUMENTS" at 904.5,-1064.84 h60
  text ".Print_Time" at 2169,-1064.84 h60
  text ".Print_Date" at 2898,-1064.84 h60
  text "GENERATED    :" at 3767.5,-1064.84 h60
  text ".plot_File_Name" at 5440.5,-1064.84 h60
  text "PLOT NAME =" at 6246,-1064.84 h60
M9 Title Sheet:
  drawing of 57 lines, arcs and shapes, not listed
  text "1" at 739.84,8036.5 h70
  text "2" at 3235.5,8036.5 h70
  text "3" at 5724.84,8036.5 h70
  text "4" at 8231.51,8036.5 h70
  text "5" at 10730.5,8036.5 h70
  text "6" at 13235.5,8036.5 h70
  text "A" at -416.5,6893.5 h70
  text "A" at 14383.5,6893.5 h70
  text "B" at -416.5,4513.5 h70
  text "B" at 14383.5,4513.5 h70
  text "C" at -416.5,2138.5 h70
  text "C" at 14383.5,2138.5 h70
  text "PROJECT TITLE:" at 11343.5,277.5 h45
  text ".PRJ_Title" at 11393.5,144.17 h70
  text "DESIGNED FOR:" at 11343.5,-23.5 h45
  text ".PRJ_Customer" at 11393.5,-163.5 h70
  text "D" at -416.5,-231.5 h70
  text "D" at 14383.5,-231.5 h70
  text "FILE NAME:" at 11343.5,-323.5 h45
  text ".PCB_File_Name_No_Path" at 11393.5,-443.5 h70
  text "Texas Instruments (TI) and/or its licensors do not warrant the accuracy or completeness of this specification" at 6374,-605.34 h45
  text "ENGINEER:" at 11343.5,-613.5 h45
  text "LAYOUT BY:" at 12848.5,-613.5 h45
  text "or any information contained therein. TI and/or its licensors do not warrant that this design will meet" at 6329.01,-718 h45
  text ".PRJ_Engineer" at 11393.5,-768.49 h70
  text ".PCB_Layout" at 12899,-768.49 h70
  text "the specifications, will be suitable for your application or fit for any particular purpose, or will operate in" at 6329.01,-830.67 h45
  text ".Layer_Name" at 577,-858.49 h60
  text "ALTIUM DESIGNER VERSION:" at 12848.5,-923.5 h45
  text "an implementation. TI and/or its licensors do not warrant that the design is production worthy. You should" at 6329.01,-943.33 h45
  text "completely validate and test your design implementation to confirm the system functionality for your application." at 6374,-1056 h45
  text ".print_Scale" at 11393.5,-1056.83 h70
  text ".Application_BuildNumber" at 12899,-1056.83 h70
  text "1" at 739.84,-1263.5 h70
  text "2" at 3235.5,-1263.5 h70
  text "3" at 5724.84,-1263.5 h70
  text "4" at 8231.51,-1263.5 h70
  text "5" at 10730.5,-1263.5 h70
  text "6" at 13235.5,-1263.5 h70
M10 Fab Notes:
  drawing of 185 lines, arcs and shapes, not listed
  text "DESIGN INFORMATION" at 12381.02,5910 h60
  text "MIN. TRACK WIDTH:" at 11736.46,5730 h60
  text "8" at 12832.7,5730 h60
  text "MIL" at 12987.46,5730 h60
  text "MIN. CLEARANCE:" at 11736.46,5598 h60
  text "0.2" at 12772.7,5598 h60
  text "mm" at 12987.46,5598 h60
  text "MIN. VIA PAD SIZE:" at 11736.46,5466 h60
  text "24" at 12802.71,5466 h60
  text "MIL" at 12987.46,5466 h60
  text "0.05mm (2MIL)" at 12431.46,5324.29 h60
  text "MINIMUM ANNULAR RING" at 11407.23,5320 h60
  text "EXTERNAL" at 13139.46,5320 h60
  text "PER" at 11607.23,5202 h60
  text "IPC-D-275 CLASS 2 LEVEL C" at 11827.23,5202 h60
  text "MIL, HOLES" at 13315.46,5089.71 h60
  text "+/-" at 12923,5089 h60
  text "+/-" at 13777,5089 h60
  text "REGISTRATION TOLERANCES:" at 11407.23,5084 h60
  text "METAL" at 12607,5084 h60
  text "5" at 13183.2,5084 h60
  text "3" at 14016.2,5084 h60
  text "MIL" at 14132.46,5084 h60
  text "MATERIAL:" at 11332.46,4874.54 h60
  text "FR-4 High Tg" at 12318.9,4734.21 h60
  text "FR-408" at 11753.46,4725.64 h60
  text "X" at 12165.46,4725.64 h60
  text "OTHER" at 13241.46,4725.64 h60
  text "62 MIL (1.6mm) +/-10%" at 12073.56,4562.92 h60
  text "THICKNESS:" at 11407.23,4558.64 h60
  text "X" at 11945.4,4558.64 h60
  text "OTHER" at 13358.46,4558.64 h60
  text "TOLERANCE:" at 11407.23,4400.64 h60
  text "X" at 12246.53,4400.64 h60
  text "ANSI IPC-6012 TYPE 3 CLASS 2" at 12433.48,4400.64 h60
  text "OTHER +/-" at 12433.46,4244.64 h60
  text "BOW & TWIST:" at 11407.23,4087.64 h60
  text "X" at 12246.53,4087.64 h60
  text "ANSI IPC-6012 TYPE 3 CLASS 2" at 12433.48,4087.64 h60
  text "OTHER +/-" at 12433.46,3929.13 h60
  text "DRILLING:" at 11332.46,3790.64 h60
  text "REFERENCE:" at 11407.23,3673.64 h60
  text "X" at 12055.46,3673.64 h60
  text "AS SHOWN" at 12242.46,3673.64 h60
  text "X" at 12956.46,3673.64 h60
  text "NC_DRILL FILES" at 13093.46,3673.64 h60
  text "PTH MIN COPPER THICKNESS:" at 11407.23,3515.64 h60
  text "X" at 12757.46,3515.64 h60
  text "1MIL" at 12894.46,3515.64 h60
  text "OTHER" at 13391.46,3515.64 h60
  text "BOARD FINISH:" at 11332.46,3356.64 h60
  text "SILKSCREEN:" at 11487.68,3238.64 h60
  text "X" at 12436.46,3238.64 h60
  text "TOP" at 12562.46,3238.64 h60
  text "BOTTOM" at 13073.46,3238.64 h60
  text "SILKSCREEN COLOR:" at 11487.68,3071.64 h60
  text "X" at 12435.42,3071.64 h60
  text "WHITE" at 12562.46,3071.64 h60
  text "OTHER" at 13073.46,3071.64 h60
  text "SOLDER RESIST COLOR:" at 11487.68,2901.64 h60
  text "X" at 12055.42,2742.44 h60
  text "GREEN" at 12182.46,2742.44 h60
  text "BLUE" at 12773.46,2742.44 h60
  text "OTHER" at 13311.46,2742.44 h60
  text "IMMERSION GOLD (ENIG)" at 12393.46,2553.92 h60
  text "ENEPIG" at 13731,2550.64 h60
  text "SURFACE FINISH:" at 11332.46,2549.64 h60
  text "X" at 12206.51,2549.64 h60
  text "IMM. TIN/SILVER OR EQUIV" at 11662,2392.64 h60
  text "OTHER" at 13093.46,2392.64 h60
  text "ARRAY/PANEL:" at 11332.46,2213.64 h60
  text "CUT AND TRIM PER MECH LAYER 1" at 12393.46,2209.35 h60
  text "N.C. ROUTE" at 12393.46,2057.64 h60
  text "X" at 13072.46,2057.64 h60
  text "V. SCORE" at 13259.46,2057.64 h60
  text "CERTIFICATION:" at 11332.46,1920.64 h60
  text "MATERIALS AND WORKMANSHIP FOR ALL PCBS" at 12057.46,1920.64 h60
  text "TO MEET OR EXCEED THE REQUIREMENTS OF:" at 12057.46,1822.64 h60
  text "X" at 11683.96,1686.13 h60
  text "ANSI IPC-A-600F CLASS ->" at 11822.96,1686.13 h60
  text "X" at 13462.02,1686.13 h60
  text "2" at 13580.96,1686.14 h60
  text "1" at 13265.96,1684.64 h60
  text "3" at 13934.96,1684.64 h60
  text "X" at 11686.02,1526.64 h60
  text "UL 94V-0" at 11822.96,1526.64 h60
  text "X" at 12498.02,1526.64 h60
  text "RoHS" at 12634.96,1526.64 h60
  text "OTHER" at 13279.36,1526.64 h60
  text "PER ORDER" at 13676.42,1526.64 h60
  text "ADDITIONAL REQUIREMENTS:" at 11332.46,1385.64 h60
  text "MICROSECTION:" at 11407.23,1270.64 h60
  text "YES" at 12312.96,1270.64 h60
  text "REQUIRED" at 13174.46,1114.49 h60
  text "BARE BOARD ELEC. TEST:" at 11407.23,1111.64 h60
  text "NONE" at 12712.96,1111.64 h60
  text "X" at 13047.46,1111.64 h60
  text "PER ORDER" at 13766.46,1111.64 h60
  text "MANUFACTURER'S UL:" at 11407.23,954.64 h60
  text "RAIL" at 12572.96,950.35 h60
  text "METAL" at 13064.77,950.35 h60
  text "X" at 13440,950 h60
  text "SILK" at 13576.46,950.35 h60
  text ".Layer_Name" at 577,-858.49 h60
M11 Gerber Information:
  lines w10: -292,-930.17 6308,-930.17 ; -292,-726.83 6310,-726.83 ; -292,-523.5 -292,-1133.5 3713,-1133.5 6310,-1133.5 6310,-523.5 -291.5,-523.5 -291.5,-1133.5 1284,-1133.5 ; 2173,-1133.5 2173,-523.5 ; 3440,-726.83 3440,-523.5 ; 4280,-726.83 4280,-523.5 ; 4902,-1140 4902,-937.17
  text "ALL ARTWORK VIEWED FROM TOP SIDE" at -228.5,-655.67 h60
  text "BOARD #:" at 2248,-655.67 h60
  text ".PRJ_Number" at 2793.5,-655.67 h60
  text "REV:" at 3638,-655.67 h60
  text ".PCB_Rev" at 3929.5,-655.67 h60
  text "SVN REV:" at 4476,-655.67 h60
  text ".VersionControl_RevNumber" at 4982,-655.67 h60
  text "LAYER NAME =" at -228.5,-858.49 h60
  text "PLOT NAME =" at -228.5,-1064.34 h60
  text ".plot_File_Name" at 577,-1064.34 h60
  text "GENERATED    :" at 2250,-1064.34 h60
  text ".Print_Date" at 3119.5,-1064.34 h60
  text ".Print_Time" at 3848.5,-1064.34 h60
  text "TEXAS INSTRUMENTS" at 5113,-1064.34 h60
M12 Stackup:
  drawing of 191 lines, arcs and shapes, not listed
  text "Layer" at 9790.34,7830 h60
  text "Name" at 10200.26,7830 h60
  text "Material" at 11130,7830 h60
  text "Thickness" at 11989.77,7830 h60
  text "Constant" at 12639.6,7830 h60
  text "Board Layer Stack" at 13209.46,7830 h60
  text "1" at 9790.34,7710 h60
  text "Top Overlay" at 10200.26,7710 h60
  text "2" at 9790.34,7590 h60
  text "Top Solder" at 10200.26,7590 h60
  text "Solder Resist" at 11130,7590 h60
  text "0.40mil" at 11989.77,7590 h60
  text "3.5" at 12639.6,7590 h60
  text "3" at 9790.34,7470 h60
  text "Top Layer" at 10200.26,7470 h60
  text "Copper" at 11130,7470 h60
  text "1.40mil" at 11989.77,7470 h60
  text "4" at 9790.34,7350 h60
  text "Dielectric1" at 10200.26,7350 h60
  text "FR-4" at 11130,7350 h60
  text "59.20mil" at 11989.77,7350 h60
  text "4.8" at 12639.6,7350 h60
  text "5" at 9790.34,7230 h60
  text "Bottom Layer" at 10200.26,7230 h60
  text "Copper" at 11130,7230 h60
  text "1.40mil" at 11989.77,7230 h60
  text "6" at 9790.34,7110 h60
  text "Bottom Solder" at 10200.26,7110 h60
  text "Solder Resist" at 11130,7110 h60
  text "0.40mil" at 11989.77,7110 h60
  text "3.5" at 12639.6,7110 h60
  text ".Layer_Name" at 577,-858.49 h60
M13 Component Bodies Top:
  text ".Layer_Name" at 577,-858.49 h60
M14 Component Bodies Bottom:
  text ".Layer_Name" at 577,-858.49 h60
M15 Courtyards Top:
  text ".Layer_Name" at 577,-858.49 h60
M16 Courtyards Bottom:
  text ".Layer_Name" at 577,-858.49 h60
Drill Drawing:
  circle w10: c5600.62,1585.83 r20
  circle w10: c5600.62,1585.83 r33.33
  lines w10: 5567.29,1469.17 5633.96,1469.17 5600.62,1402.5 5567.29,1469.17 ; 5567.29,1719.17 5583.96,1719.17 5600.62,1702.5 5617.29,1719.17 5633.96,1719.17 5617.29,1735.83 5633.96,1752.5 5617.29,1752.5 5600.62,1769.17 5583.96,1752.5 5567.29,1752.5 5583.96,1735.83 5567.29,1719.17 ; 5567.29,1852.5 5600.62,1869.17 5633.96,1852.5 5617.29,1885.83 5633.96,1919.17 5600.62,1902.5 5567.29,1919.17 5583.96,1885.83 5567.29,1852.5 ; 5567.29,2019.17 5583.96,2019.17 5583.96,2002.5 5617.29,2002.5 5617.29,2019.17 5633.96,2019.17 5633.96,2052.5 5617.29,2052.5 5617.29,2069.17 5583.96,2069.17 5583.96,2052.5 5567.29,2052.5 5567.29,2019.17 ; 5567.29,2452.5 5567.29,2469.17 5583.96,2485.83 5567.29,2502.5 5567.29,2519.17 5583.96,2519.17 5600.62,2502.5 5617.29,2519.17 5633.96,2519.17 5633.96,2502.5 5617.29,2485.83 5633.96,2469.17 5633.96,2452.5 5617.29,2452.5 5600.62,2469.17 5583.96,2452.5 5567.29,2452.5 ; 5580.62,1455.83 5620.62,1455.83 5600.62,1415.83 5580.62,1455.83 ; 5580.62,1725.83 5590.62,1725.83 5600.62,1715.83 5610.62,1725.83 5620.62,1725.83 5610.62,1735.83 5620.62,1745.83 5610.62,1745.83 5600.62,1755.83 5590.62,1745.83 5580.62,1745.83 5590.62,1735.83 5580.62,1725.83 ; 5580.62,1865.83 5600.62,1875.83 5620.62,1865.83 5610.62,1885.83 5620.62,1905.83 5600.62,1895.83 5580.62,1905.83 5590.62,1885.83 5580.62,1865.83 ; 5580.62,2025.83 5590.62,2025.83 5590.62,2015.83 5610.62,2015.83 5610.62,2025.83 5620.62,2025.83 5620.62,2045.83 5610.62,2045.83 5610.62,2055.83 5590.62,2055.83 5590.62,2045.83 5580.62,2045.83 5580.62,2025.83 ; 5580.62,2465.83 5580.62,2475.83 5590.62,2485.83 5580.62,2495.83 5580.62,2505.83 5590.62,2505.83 5600.62,2495.83 5610.62,2505.83 5620.62,2505.83 5620.62,2495.83 5610.62,2485.83 5620.62,2475.83 5620.62,2465.83 5610.62,2465.83 5600.62,2475.83 5590.62,2465.83 5580.62,2465.83
  lines w15: 5507.5,1357.5 9386.47,1357.5 ; 5507.5,2707.5 9386.47,2707.5 ; 6058.38,1207.5 6058.38,2857.5 ; 6756.19,1207.5 6756.19,2857.5 ; 8101.79,1207.5 8101.79,2857.5 ; 8607.67,1207.5 8607.67,2857.5 ; 5507.5,1207.5 9386.47,1207.5 9386.47,2857.5 5507.5,2857.5 5507.5,1207.5
  text "Symbol" at 5597.5,2752.5 h72
  text "Hit Count" at 6103.38,2752.5 h72
  text "Finished Hole Size" at 6801.19,2752.5 h72
  text "Plated" at 8146.79,2752.5 h72
  text "Hole Type" at 8652.67,2752.5 h72
  text "5" at 6103.38,2602.5 h60
  text "7.87mil (0.200mm)" at 6801.19,2602.5 h60
  text "PTH" at 8146.79,2602.5 h60
  text "Round" at 8652.67,2602.5 h60
  text "C" at 5568.41,2592.51 h66.67
  text "41" at 6103.38,2452.5 h60
  text "10.00mil (0.254mm)" at 6801.19,2452.5 h60
  text "PTH" at 8146.79,2452.5 h60
  text "Round" at 8652.67,2452.5 h60
  text "22" at 6103.38,2302.5 h60
  text "18.00mil (0.457mm)" at 6801.19,2302.5 h60
  text "PTH" at 8146.79,2302.5 h60
  text "Round" at 8652.67,2302.5 h60
  text "A" at 5568.41,2292.51 h66.67
  text "3" at 6103.38,2152.5 h60
  text "28.00mil (0.711mm)" at 6801.19,2152.5 h60
  text "PTH" at 8146.79,2152.5 h60
  text "Round" at 8652.67,2152.5 h60
  text "B" at 5568.41,2142.51 h66.67
  text "2" at 6103.38,2002.5 h60
  text "29.53mil (0.750mm)" at 6801.19,2002.5 h60
  text "PTH" at 8146.79,2002.5 h60
  text "Round" at 8652.67,2002.5 h60
  text "10" at 6103.38,1852.5 h60
  text "35.43mil (0.900mm)" at 6801.19,1852.5 h60
  text "PTH" at 8146.79,1852.5 h60
  text "Round" at 8652.67,1852.5 h60
  text "18" at 6103.38,1702.5 h60
  text "40.00mil (1.016mm)" at 6801.19,1702.5 h60
  text "PTH" at 8146.79,1702.5 h60
  text "Round" at 8652.67,1702.5 h60
  text "4" at 6103.38,1552.5 h60
  text "50.00mil (1.270mm)" at 6801.19,1552.5 h60
  text "PTH" at 8146.79,1552.5 h60
  text "Round" at 8652.67,1552.5 h60
  text "8" at 6103.38,1402.5 h60
  text "63.00mil (1.600mm)" at 6801.19,1402.5 h60
  text "PTH" at 8146.79,1402.5 h60
  text "Round" at 8652.67,1402.5 h60
  text "113 Total" at 6103.38,1252.5 h60
  text ".Layer_Name" at 577,-858.49 h60

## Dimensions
0,0 to 0,2250 on M1 Board Outline
0,2250 to 3250,2250 on M1 Board Outline
0,-400 to 1000,-400 on M2 Board Dimensions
